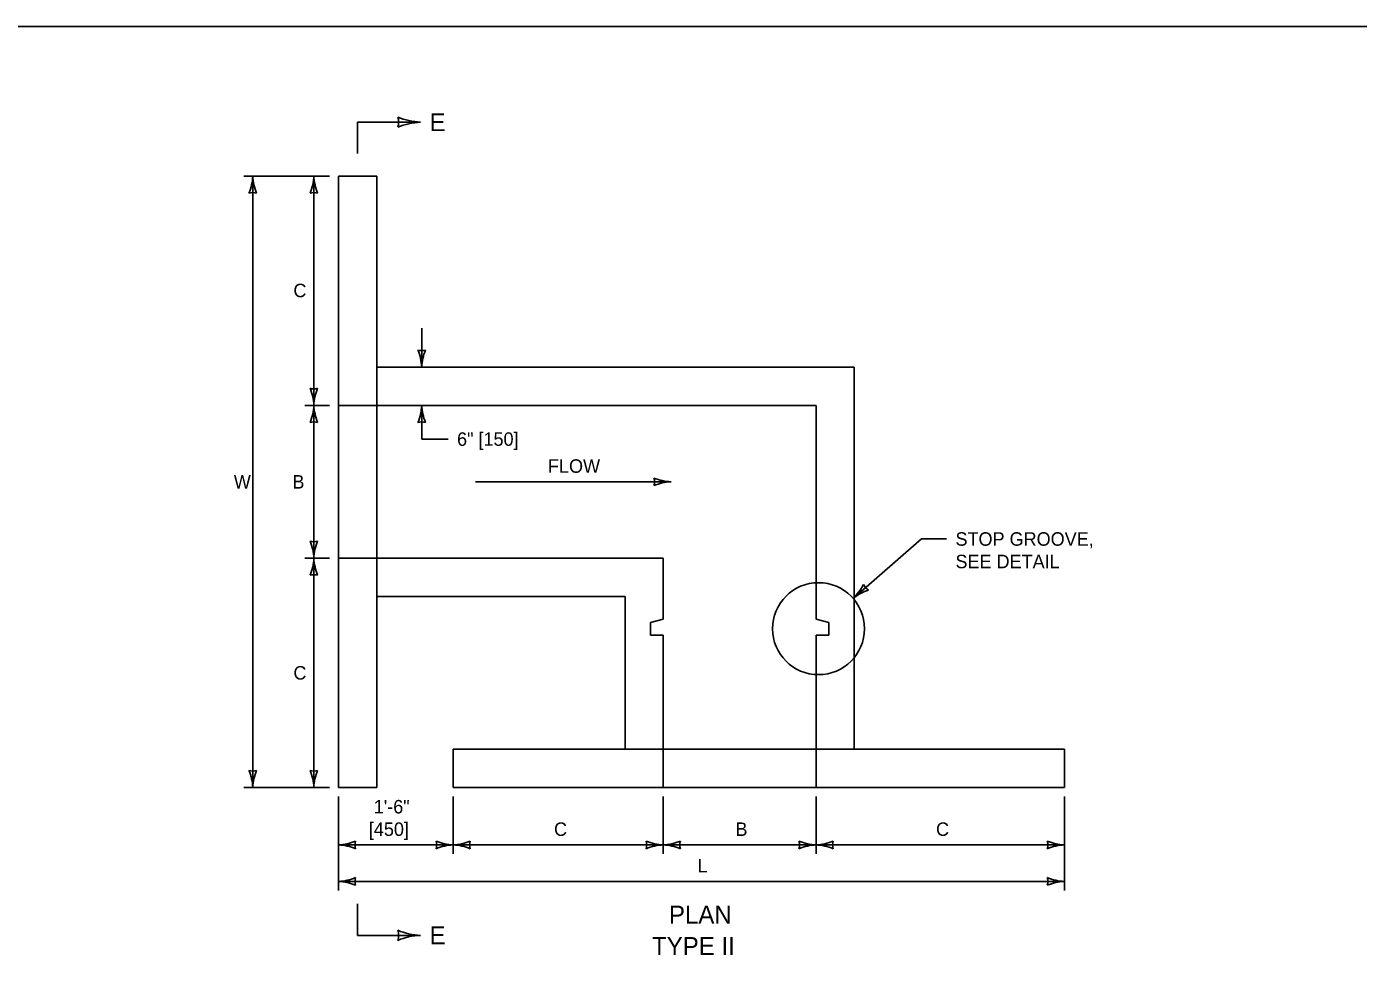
# Model space of a CAD drawing. Extents: x 49991.4 to 50021, y 49987.6 to 50011.4.
# Drawn here: x 50004.99 to 50010.91, y 49994.78 to 49999 of the extents above; entities that cross this region are included whole.
import ezdxf

# ---------------------------------------------------------------- set-up
doc = ezdxf.new("R2010")
doc.units = 0
for name, color, linetype in [('Level 1', 7, 'Continuous'), ('Level 2', 7, 'Continuous'), ('Level 3', 7, 'Continuous'), ('Level 4', 7, 'Continuous'), ('Level 6', 7, 'Continuous')]:
    doc.layers.add(name, color=color, linetype=linetype)

msp = doc.modelspace()

# ---------------------------------------------------------------- linework, layer by layer
at = {"layer": 'Level 1'}
for p, q in [((50006.3742, 49995.614), (50006.3742, 49998.3342)), ((50006.3742, 49998.3342), (50006.5442, 49998.3342)), ((50006.5442, 49998.3342), (50006.5442, 49997.4842)), ((50006.5442, 49997.4842), (50008.6692, 49997.4842)), ((50008.6692, 49997.4842), (50008.6692, 49995.784)), ((50006.3742, 49997.3142), (50008.4992, 49997.3142)), ((50008.4992, 49997.3142), (50008.4992, 49996.363)), ((50006.3742, 49996.6342), (50007.8192, 49996.6342)), ((50007.8192, 49996.6342), (50007.8192, 49996.363)), ((50006.5442, 49996.4642), (50006.5442, 49995.614)), ((50006.5442, 49996.4642), (50007.6492, 49996.4642)), ((50007.6492, 49996.4642), (50007.6492, 49995.784)), ((50007.8192, 49996.363), (50007.7626, 49996.3488)), ((50007.7626, 49996.3488), (50007.7626, 49996.2922)), ((50008.4992, 49996.363), (50008.5558, 49996.3488)), ((50008.5558, 49996.3488), (50008.5558, 49996.2922)), ((50007.7626, 49996.2922), (50007.8192, 49996.2922)), ((50007.8192, 49996.2922), (50007.8192, 49995.614)), ((50008.5558, 49996.2922), (50008.4992, 49996.2922)), ((50008.4992, 49996.2922), (50008.4992, 49995.614)), ((50006.8842, 49995.784), (50007.6492, 49995.784)), ((50006.8842, 49995.784), (50006.8842, 49995.614)), ((50008.6692, 49995.784), (50009.6042, 49995.784)), ((50009.6042, 49995.784), (50009.6042, 49995.614)), ((50006.3742, 49995.614), (50006.5442, 49995.614)), ((50006.8842, 49995.614), (50009.6042, 49995.614))]:
    msp.add_line(p, q, dxfattribs=at)
msp.add_lwpolyline([(49999.3835, 49998.9992), (50016.7501, 49998.9992), (50016.7501, 49987.7988), (49999.3835, 49987.7988)], close=True, dxfattribs=at)
at = {"layer": 'Level 3'}
for p, q in [((50006.3342, 49998.3342), (50005.9524, 49998.3342)), ((50005.9924, 49998.3342), (50005.9924, 49995.614)), ((50006.2642, 49998.3342), (50006.2642, 49995.614)), ((50006.7442, 49997.4842), (50006.7442, 49997.6576)), ((50006.3342, 49997.3142), (50006.2242, 49997.3142)), ((50006.7442, 49997.3142), (50006.7442, 49997.1642)), ((50006.7442, 49997.1642), (50006.8615, 49997.1642)), ((50006.9832, 49996.9742), (50007.8536, 49996.9742)), ((50008.9677, 49996.7197), (50008.6645, 49996.4552)), ((50008.9677, 49996.7197), (50009.0796, 49996.7197)), ((50006.3342, 49996.6342), (50006.2242, 49996.6342)), ((50006.3342, 49995.614), (50005.9524, 49995.614)), ((50006.3742, 49995.574), (50006.3742, 49995.1563)), ((50006.8842, 49995.574), (50006.8842, 49995.3187)), ((50007.8192, 49995.574), (50007.8192, 49995.3187)), ((50008.4992, 49995.574), (50008.4992, 49995.3187)), ((50009.6042, 49995.574), (50009.6042, 49995.1563)), ((50009.6042, 49995.3587), (50006.3742, 49995.3587)), ((50006.3742, 49995.1963), (50009.6042, 49995.1963))]:
    msp.add_line(p, q, dxfattribs=at)
msp.add_circle((50008.5102, 49996.3207), 0.2046, dxfattribs=at)
for centre, radius, start, end in [((50006.7514, 49998.8704), 0.2964, 247.45601, 267.63952), ((50006.5682, 49998.5742), 0.073, 342.13882, 17.86118), ((50006.7545, 49998.2639), 0.3107, 92.82731, 112.07716), ((50005.7703, 49998.3434), 0.2223, 337.45601, 357.63952), ((50006.2251, 49998.3457), 0.233, 182.82731, 202.07716), ((50006.0421, 49998.3434), 0.2223, 337.45601, 357.63952), ((50006.4969, 49998.3457), 0.233, 182.82731, 202.07716), ((50005.9924, 49998.206), 0.0548, 72.13882, 107.86118), ((50006.2642, 49998.206), 0.0548, 72.13882, 107.86118), ((50006.7442, 49997.6124), 0.0548, 252.13882, 287.86118), ((50006.5115, 49997.4727), 0.233, 2.82731, 22.07716), ((50006.9663, 49997.475), 0.2223, 157.45601, 177.63952), ((50006.2642, 49997.4424), 0.0548, 252.13882, 287.86118), ((50006.0315, 49997.3027), 0.233, 2.82731, 22.07716), ((50006.4863, 49997.305), 0.2223, 157.45601, 177.63952), ((50006.0421, 49997.3234), 0.2223, 337.45601, 357.63952), ((50006.4969, 49997.3257), 0.233, 182.82731, 202.07716), ((50006.5221, 49997.3234), 0.2223, 337.45601, 357.63952), ((50006.9769, 49997.3257), 0.233, 182.82731, 202.07716), ((50006.2642, 49997.186), 0.0548, 72.13882, 107.86118), ((50006.7442, 49997.186), 0.0548, 72.13882, 107.86118), ((50007.8628, 49997.1963), 0.2223, 247.45601, 267.63952), ((50007.7254, 49996.9742), 0.0548, 342.13882, 17.86118), ((50007.8651, 49996.7415), 0.233, 92.82731, 112.07716), ((50006.2642, 49996.7624), 0.0548, 252.13882, 287.86118), ((50006.0315, 49996.6227), 0.233, 2.82731, 22.07716), ((50006.4863, 49996.625), 0.2223, 157.45601, 177.63952), ((50006.0421, 49996.6434), 0.2223, 337.45601, 357.63952), ((50006.4969, 49996.6457), 0.233, 182.82731, 202.07716), ((50006.2642, 49996.506), 0.0548, 72.13882, 107.86118), ((50008.5026, 49996.6228), 0.233, 314.00062, 333.25047), ((50008.8038, 49996.282), 0.2223, 108.62932, 128.81283), ((50008.761, 49996.5396), 0.0548, 203.31213, 239.03449), ((50005.9924, 49995.7422), 0.0548, 252.13882, 287.86118), ((50005.7597, 49995.6025), 0.233, 2.82731, 22.07716), ((50006.2145, 49995.6048), 0.2223, 157.45601, 177.63952), ((50006.2642, 49995.7422), 0.0548, 252.13882, 287.86118), ((50006.0315, 49995.6025), 0.233, 2.82731, 22.07716), ((50006.4863, 49995.6048), 0.2223, 157.45601, 177.63952), ((50006.3627, 49995.5914), 0.233, 272.82731, 292.07716), ((50006.365, 49995.1366), 0.2223, 67.45601, 87.63952), ((50006.5024, 49995.3587), 0.0548, 162.13882, 197.86118), ((50006.756, 49995.3587), 0.0548, 342.13882, 17.86118), ((50006.8957, 49995.5914), 0.233, 247.92284, 267.17269), ((50006.8934, 49995.1366), 0.2223, 92.36048, 112.54399), ((50006.8727, 49995.5914), 0.233, 272.82731, 292.07716), ((50006.875, 49995.1366), 0.2223, 67.45601, 87.63952), ((50007.0124, 49995.3587), 0.0548, 162.13882, 197.86118), ((50007.8284, 49995.5808), 0.2223, 247.45601, 267.63952), ((50007.691, 49995.3587), 0.0548, 342.13882, 17.86118), ((50007.8307, 49995.126), 0.233, 92.82731, 112.07716), ((50007.8077, 49995.5914), 0.233, 272.82731, 292.07716), ((50007.81, 49995.1366), 0.2223, 67.45601, 87.63952), ((50007.9474, 49995.3587), 0.0548, 162.13882, 197.86118), ((50008.5084, 49995.5808), 0.2223, 247.45601, 267.63952), ((50008.371, 49995.3587), 0.0548, 342.13882, 17.86118), ((50008.5107, 49995.126), 0.233, 92.82731, 112.07716), ((50008.4877, 49995.5914), 0.233, 272.82731, 292.07716), ((50008.49, 49995.1366), 0.2223, 67.45601, 87.63952), ((50008.6274, 49995.3587), 0.0548, 162.13882, 197.86118), ((50009.6134, 49995.5808), 0.2223, 247.45601, 267.63952), ((50009.476, 49995.3587), 0.0548, 342.13882, 17.86118), ((50009.6157, 49995.126), 0.233, 92.82731, 112.07716), ((50006.3627, 49995.429), 0.233, 272.82731, 292.07716), ((50006.365, 49994.9742), 0.2223, 67.45601, 87.63952), ((50006.5024, 49995.1963), 0.0548, 162.13882, 197.86118), ((50009.6134, 49995.4184), 0.2223, 247.45601, 267.63952), ((50009.476, 49995.1963), 0.0548, 342.13882, 17.86118), ((50009.6157, 49994.9636), 0.233, 92.82731, 112.07716), ((50006.5682, 49994.9563), 0.073, 342.13882, 17.86118), ((50006.7545, 49995.2666), 0.3107, 247.92284, 267.17269), ((50006.7514, 49994.6601), 0.2964, 92.36048, 112.54399)]:
    msp.add_arc(centre, radius, start, end, dxfattribs=at)
at = {"layer": 'Level 4'}
for p, q in [((50006.5442, 49996.4642), (50006.5442, 49997.4842)), ((50007.6492, 49995.784), (50008.6692, 49995.784))]:
    msp.add_line(p, q, dxfattribs=at)
at = {"layer": 'Level 6'}
for p, q in [((50006.4592, 49998.5742), (50006.7392, 49998.5742)), ((50006.4592, 49998.5742), (50006.4592, 49998.4342)), ((50006.4592, 49994.9563), (50006.4592, 49995.0963)), ((50006.4592, 49994.9563), (50006.7392, 49994.9563))]:
    msp.add_line(p, q, dxfattribs=at)

# ---------------------------------------------------------------- texts
at = {"layer": 'Level 2'}
for s, height, p in [('E', 0.08, (50006.7792, 49998.5342)), ('C', 0.06, (50006.1732, 49997.7954)), ('6" [150]', 0.06, (50006.9015, 49997.1342)), ('FLOW', 0.06, (50007.3062, 49997.0142)), ('W', 0.06, (50005.908, 49996.9441)), ('B', 0.06, (50006.1687, 49996.9441)), ('STOP GROOVE,', 0.06, (50009.1196, 49996.6897)), ('SEE DETAIL', 0.06, (50009.1196, 49996.5897)), ('C', 0.06, (50006.1732, 49996.0942)), ('1\'-6"', 0.06, (50006.5308, 49995.4987)), ('[450]', 0.06, (50006.509, 49995.3987)), ('C', 0.06, (50007.3331, 49995.3987)), ('B', 0.06, (50008.1406, 49995.3987)), ('C', 0.06, (50009.0331, 49995.3987)), ('L', 0.06, (50007.9722, 49995.2363)), ('PLAN', 0.08, (50007.8443, 49995.0087)), ('E', 0.08, (50006.7792, 49994.9163)), ('TYPE II', 0.08, (50007.7691, 49994.8687))]:
    msp.add_text(s, height=height, dxfattribs=at).set_placement(p)

doc.saveas('drawing.dxf')
